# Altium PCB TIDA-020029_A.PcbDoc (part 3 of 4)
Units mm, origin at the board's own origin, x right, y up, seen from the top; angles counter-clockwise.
Board outline 267.5 x 53.5 mm, 2 copper layers (Top Layer, Bottom Layer), stack 1.575 mm thick; 255 components, 134 nets, 990 pads, 1977 vias.
Unrouted connection lines stored in the file: 9.
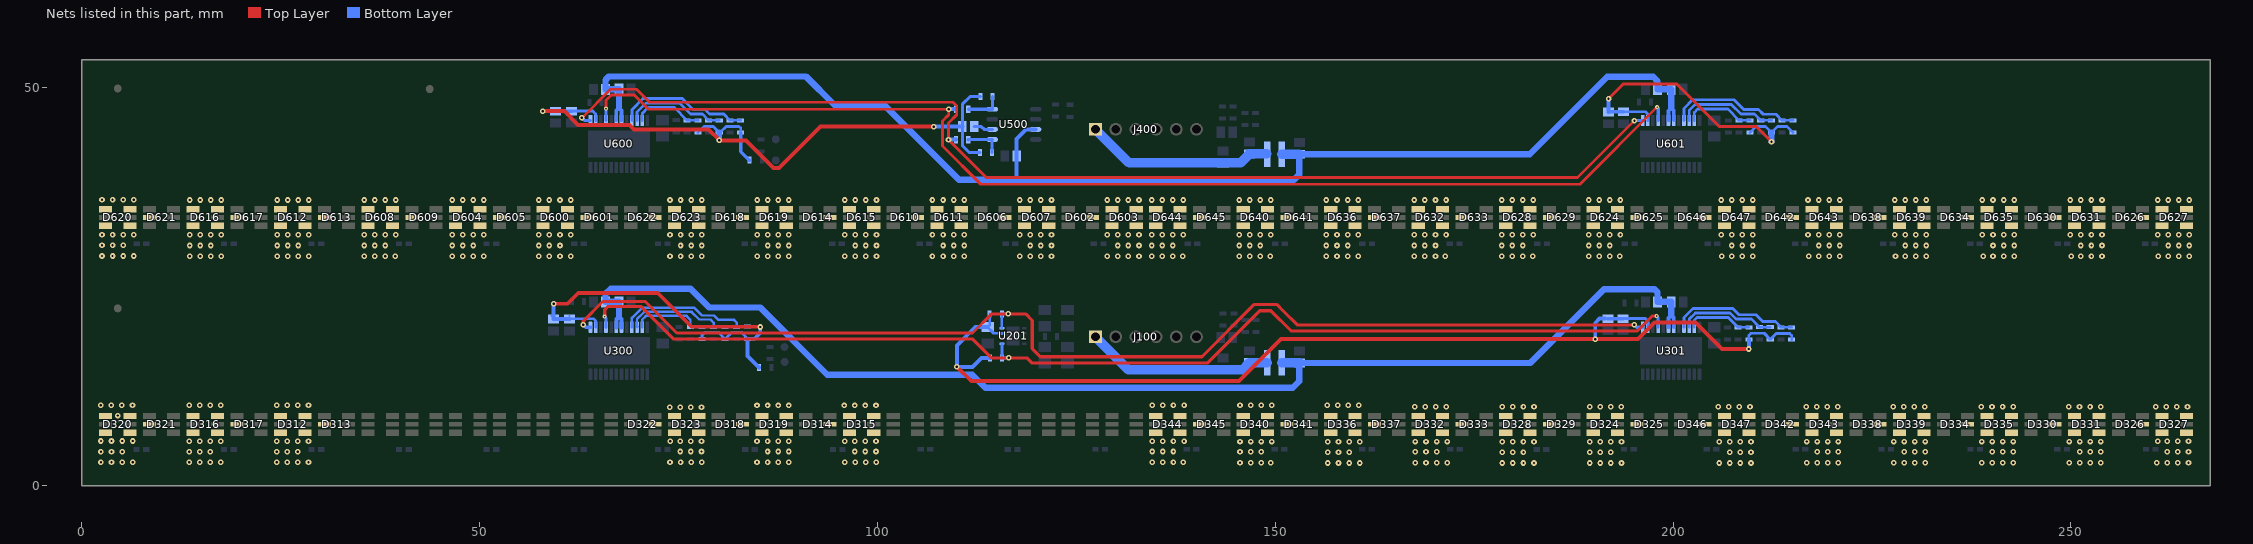
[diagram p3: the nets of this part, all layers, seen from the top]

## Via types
v1: diameter 0.7, hole 0.3, Top Layer to Bottom Layer, tented both sides, 1881 vias
v2: diameter 0.5, hole 0.2, Top Layer to Bottom Layer, tented both sides, 96 vias

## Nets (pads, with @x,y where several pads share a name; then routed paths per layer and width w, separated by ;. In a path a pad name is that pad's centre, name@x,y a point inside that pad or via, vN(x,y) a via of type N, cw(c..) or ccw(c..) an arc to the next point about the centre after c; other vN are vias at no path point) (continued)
NetD312_1: D312.1 D312.3 D312.4 D312.6 D313.2
  other v1: 24.486,2.908 25.815,2.908 27.144,2.908 28.473,2.908 24.486,4.256 25.815,4.256 27.144,4.256 24.486,5.577 25.815,5.577 27.144,5.577 28.473,5.577 24.486,10.098 25.815,10.098 27.144,10.098 28.473,10.098
NetD314_2: D314.2 D315.1 D315.3 D315.4 D315.6
  other v1: 95.86,2.913 97.189,2.913 98.518,2.913 99.847,2.913 97.148,4.281 98.478,4.281 99.807,4.281 95.86,5.577 97.148,5.577 98.478,5.577 99.807,5.577 95.819,10.073 97.148,10.073 98.478,10.073 99.807,10.073
NetD316_1: D316.1 D316.3 D316.4 D316.6 D317.2
  other v1: 13.462,2.908 14.791,2.908 16.121,2.908 17.45,2.908 13.462,4.256 14.791,4.256 16.121,4.256 13.462,5.577 14.791,5.577 16.121,5.577 17.45,5.577 13.462,10.098 14.791,10.098 16.121,10.098 17.45,10.098
NetD318_2: D318.2 D319.1 D319.3 D319.4 D319.6
  other v1: 84.85,2.908 86.179,2.908 87.509,2.908 88.838,2.908 86.179,4.281 87.509,4.281 88.838,4.281 84.85,5.577 86.179,5.577 87.509,5.577 88.838,5.577 84.85,10.073 86.179,10.073 87.509,10.073 88.838,10.073
NetD320_1: D320.1 D320.3 D320.4 D320.6 D321.2
  other v1: 2.388,2.908 3.717,2.908 5.046,2.908 6.375,2.908 2.388,4.256 3.717,4.256 5.046,4.256 2.388,5.602 3.717,5.602 5.046,5.602 6.375,5.602 4.5,8.803 2.362,10.098 3.691,10.098 5.021,10.098 6.35,10.098
NetD322_2: D322.2 D323.1 D323.3 D323.4 D323.6
  other v1: 73.914,2.908 75.243,2.908 76.573,2.908 77.902,2.908 75.218,4.281 76.547,4.281 77.876,4.281 73.939,5.577 75.218,5.577 76.547,5.577 77.876,5.577 73.889,9.869 75.218,9.869 76.547,9.869 77.876,9.869
NetD324_1: D324.1 D324.3 D324.4 D324.6 D325.2
  other v1: 189.535,2.84 190.864,2.84 192.193,2.84 193.523,2.84 189.535,4.213 190.864,4.213 192.193,4.213 189.535,5.509 190.864,5.509 192.193,5.509 193.523,5.509 189.509,9.898 190.839,9.898 192.168,9.898 193.497,9.898
NetD326_2: D326.2 D327.1 D327.3 D327.4 D327.6
  other v1: 260.807,2.892 262.136,2.892 263.466,2.892 264.795,2.892 262.136,4.264 263.466,4.264 264.795,4.264 260.907,5.559 262.136,5.559 263.466,5.559 264.795,5.559 260.68,9.898 262.009,9.898 263.339,9.898 264.668,9.898
NetD328_1: D328.1 D328.3 D328.4 D328.6 D329.2
  other v1: 178.537,2.84 179.866,2.84 181.195,2.84 182.524,2.84 178.537,4.213 179.866,4.213 181.195,4.213 178.537,5.509 179.866,5.509 181.195,5.509 182.524,5.509 178.537,9.898 179.866,9.898 181.195,9.898 182.524,9.898
NetD330_2: D330.2 D331.1 D331.3 D331.4 D331.6
  other v1: 249.784,2.867 251.113,2.867 252.442,2.867 253.771,2.867 251.113,4.239 252.442,4.239 253.771,4.239 249.784,5.534 251.113,5.534 252.442,5.534 253.771,5.534 249.758,9.898 251.087,9.898 252.417,9.898 253.746,9.898
NetD332_1: D332.1 D332.3 D332.4 D332.6 D333.2
  other v1: 167.615,2.865 168.944,2.865 170.273,2.865 171.602,2.865 167.615,4.239 168.944,4.239 170.273,4.239 167.615,5.534 168.944,5.534 170.273,5.534 171.602,5.534 167.513,9.898 168.842,9.898 170.172,9.898 171.501,9.898
NetD334_2: D334.2 D335.1 D335.3 D335.4 D335.6
  other v1: 238.785,2.867 240.115,2.867 241.444,2.867 242.773,2.867 240.115,4.239 241.444,4.239 242.773,4.239 238.785,5.534 240.115,5.534 241.444,5.534 242.773,5.534 238.76,9.898 240.089,9.898 241.419,9.898 242.748,9.898
NetD336_1: D336.1 D336.3 D336.4 D336.6 D337.2
  other v1: 156.616,2.84 157.946,2.84 159.275,2.84 160.604,2.84 156.616,4.213 157.946,4.213 159.275,4.213 156.616,5.509 157.946,5.509 159.275,5.509 160.604,5.509 156.515,10.098 157.844,10.098 159.173,10.098 160.503,10.098
NetD338_2: D338.2 D339.1 D339.3 D339.4 D339.6
  other v1: 227.736,2.867 229.066,2.867 230.395,2.867 231.724,2.867 229.066,4.239 230.395,4.239 231.724,4.239 227.736,5.534 229.066,5.534 230.395,5.534 231.724,5.534 227.66,9.898 228.989,9.898 230.319,9.898 231.648,9.898
NetD340_1: D340.1 D340.3 D340.4 D340.6 D341.2
  other v1: 145.567,2.865 146.897,2.865 148.226,2.865 149.455,2.865 145.567,4.239 146.897,4.239 148.226,4.239 145.567,5.534 146.897,5.534 148.226,5.534 149.555,5.534 145.567,10.098 146.897,10.098 148.226,10.098 149.555,10.098
NetD342_2: D342.2 D343.1 D343.3 D343.4 D343.6
  other v1: 216.786,2.867 218.115,2.867 219.445,2.867 220.774,2.867 218.115,4.239 219.445,4.239 220.774,4.239 216.786,5.534 218.115,5.534 219.445,5.534 220.774,5.534 216.738,9.898 218.067,9.898 219.397,9.898 220.726,9.898
NetD344_1: D344.1 D344.3 D344.4 D344.6 D345.2
  other v1: 134.544,2.908 135.873,2.908 137.202,2.908 138.432,2.908 134.544,4.281 135.873,4.281 137.202,4.281 134.544,5.577 135.873,5.577 137.202,5.577 138.532,5.577 134.544,10.098 135.873,10.098 137.202,10.098 138.532,10.098
NetD346_2: D346.2 D347.1 D347.3 D347.4 D347.6
  other v1: 205.811,2.842 207.141,2.842 208.47,2.842 209.799,2.842 207.141,4.213 208.47,4.213 209.799,4.213 205.811,5.509 207.141,5.509 208.47,5.509 209.799,5.509 205.685,9.898 207.014,9.898 208.344,9.898 209.673,9.898
NetD600_1: D600.1 D600.3 D600.4 D600.6 D601.2
  other v1: 57.429,28.834 58.758,28.834 60.087,28.834 61.417,28.834 57.429,30.182 58.758,30.182 60.087,30.182 57.429,31.528 58.758,31.528 60.087,31.528 61.417,31.528 57.429,35.897 58.758,35.897 60.087,35.897 61.417,35.897
NetD602_2: D602.2 D603.1 D603.3 D603.4 D603.6
  other v1: 128.88,28.834 130.209,28.834 131.538,28.834 132.867,28.834 130.209,30.182 131.538,30.182 132.867,30.182 128.88,31.528 130.209,31.528 131.538,31.528 132.867,31.528 128.88,35.897 130.209,35.897 131.538,35.897 132.867,35.897
NetD604_1: D604.1 D604.3 D604.4 D604.6 D605.2
  other v1: 46.526,28.834 47.855,28.834 49.184,28.834 50.514,28.834 46.526,30.182 47.855,30.182 49.184,30.182 46.526,31.528 47.855,31.528 49.184,31.528 50.514,31.528 46.526,35.897 47.855,35.897 49.184,35.897 50.514,35.897
NetD606_2: D606.2 D607.1 D607.3 D607.4 D607.6
  other v1: 117.881,28.834 119.211,28.834 120.54,28.834 121.869,28.834 119.211,30.182 120.54,30.182 121.869,30.182 117.881,31.528 119.211,31.528 120.54,31.528 121.869,31.528 117.881,35.897 119.211,35.897 120.54,35.897 121.869,35.897
NetD608_1: D608.1 D608.3 D608.4 D608.6 D609.2
  other v1: 35.479,28.834 36.808,28.834 38.137,28.834 39.367,28.834 35.479,30.182 36.808,30.182 38.137,30.182 35.479,31.528 36.808,31.528 38.137,31.528 39.467,31.528 35.479,35.897 36.808,35.897 38.137,35.897 39.467,35.897
NetD610_2: D610.2 D611.1 D611.3 D611.4 D611.6
  other v1: 106.909,28.834 108.238,28.834 109.567,28.834 110.896,28.834 108.238,30.182 109.567,30.182 110.896,30.182 106.909,31.528 108.238,31.528 109.567,31.528 110.896,31.528 106.909,35.897 108.238,35.897 109.567,35.897 110.896,35.897
NetD612_1: D612.1 D612.3 D612.4 D612.6 D613.2
  other v1: 24.529,28.834 25.859,28.834 27.188,28.834 28.517,28.834 24.529,30.182 25.859,30.182 27.188,30.182 24.529,31.528 25.859,31.528 27.188,31.528 28.517,31.528 24.529,35.897 25.859,35.897 27.188,35.897 28.517,35.897
NetD614_2: D614.2 D615.1 D615.3 D615.4 D615.6
  other v1: 95.885,28.834 97.214,28.834 98.544,28.834 99.873,28.834 97.214,30.182 98.544,30.182 99.873,30.182 95.885,31.528 97.214,31.528 98.544,31.528 99.873,31.528 95.885,35.897 97.214,35.897 98.544,35.897 99.873,35.897
NetD616_1: D616.1 D616.3 D616.4 D616.6 D617.2
  other v1: 13.531,28.834 14.86,28.834 16.19,28.834 17.519,28.834 13.531,30.182 14.86,30.182 16.19,30.182 13.531,31.528 14.86,31.528 16.19,31.528 17.519,31.528 13.531,35.897 14.86,35.897 16.19,35.897 17.519,35.897
NetD618_2: D618.2 D619.1 D619.3 D619.4 D619.6
  other v1: 84.861,28.834 86.191,28.834 87.52,28.834 88.849,28.834 86.191,30.182 87.52,30.182 88.849,30.182 84.861,31.528 86.191,31.528 87.52,31.528 88.849,31.528 84.861,35.897 86.191,35.897 87.52,35.897 88.849,35.897
NetD620_1: D620.1 D620.3 D620.4 D620.6 D621.2
  other v1: 2.515,28.859 3.844,28.859 5.173,28.859 6.502,28.859 2.515,30.207 3.844,30.207 5.173,30.207 2.515,31.553 3.844,31.553 5.173,31.553 6.502,31.553 2.515,35.922 3.844,35.922 5.173,35.922 6.502,35.922
NetD622_2: D622.2 D623.1 D623.3 D623.4 D623.6
  other v1: 73.914,28.834 75.243,28.834 76.573,28.834 77.902,28.834 75.243,30.182 76.573,30.182 77.902,30.182 73.914,31.528 75.243,31.528 76.573,31.528 77.902,31.528 73.914,35.897 75.243,35.897 76.573,35.897 77.902,35.897
NetD624_1: D624.1 D624.3 D624.4 D624.6 D625.2
  other v1: 189.401,28.834 190.73,28.834 192.059,28.834 193.289,28.834 189.401,30.182 190.73,30.182 192.059,30.182 189.401,31.528 190.73,31.528 192.059,31.528 193.389,31.528 189.401,35.897 190.73,35.897 192.059,35.897 193.389,35.897
NetD626_2: D626.2 D627.1 D627.3 D627.4 D627.6
  other v1: 261.009,28.834 262.238,28.834 263.567,28.834 264.897,28.834 262.238,30.182 263.567,30.182 264.897,30.182 260.909,31.528 262.238,31.528 263.567,31.528 264.897,31.528 260.909,35.897 262.238,35.897 263.567,35.897 264.897,35.897
NetD628_1: D628.1 D628.3 D628.4 D628.6 D629.2
  other v1: 178.453,28.834 179.783,28.834 181.112,28.834 182.341,28.834 178.453,30.182 179.783,30.182 181.112,30.182 178.453,31.528 179.783,31.528 181.112,31.528 182.441,31.528 178.453,35.897 179.783,35.897 181.112,35.897 182.441,35.897
NetD630_2: D630.2 D631.1 D631.3 D631.4 D631.6
  other v1: 250.036,28.834 251.265,28.834 252.595,28.834 253.924,28.834 251.265,30.182 252.595,30.182 253.924,30.182 249.936,31.528 251.265,31.528 252.595,31.528 253.924,31.528 249.936,35.897 251.265,35.897 252.595,35.897 253.924,35.897
NetD632_1: D632.1 D632.3 D632.4 D632.6 D633.2
  other v1: 167.479,28.834 168.808,28.834 170.137,28.834 171.367,28.834 167.479,30.182 168.808,30.182 170.137,30.182 167.479,31.528 168.808,31.528 170.137,31.528 171.467,31.528 167.479,35.897 168.808,35.897 170.137,35.897 171.467,35.897
NetD634_2: D634.2 D635.1 D635.3 D635.4 D635.6
  other v1: 238.987,28.834 240.216,28.834 241.546,28.834 242.875,28.834 240.216,30.182 241.546,30.182 242.875,30.182 238.887,31.528 240.216,31.528 241.546,31.528 242.875,31.528 238.887,35.897 240.216,35.897 241.546,35.897 242.875,35.897
NetD636_1: D636.1 D636.3 D636.4 D636.6 D637.2
  other v1: 156.429,28.834 157.758,28.834 159.087,28.834 160.417,28.834 156.429,30.182 157.758,30.182 159.087,30.182 156.429,31.528 157.758,31.528 159.087,31.528 160.417,31.528 156.429,35.897 157.758,35.897 159.087,35.897 160.417,35.897
NetD638_2: D638.2 D639.1 D639.3 D639.4 D639.6
  other v1: 227.963,28.834 229.193,28.834 230.522,28.834 231.851,28.834 229.193,30.182 230.522,30.182 231.851,30.182 227.863,31.528 229.193,31.528 230.522,31.528 231.851,31.528 227.863,35.897 229.193,35.897 230.522,35.897 231.851,35.897
NetD640_1: D640.1 D640.3 D640.4 D640.6 D641.2
  other v1: 145.459,28.834 146.788,28.834 148.117,28.834 149.347,28.834 145.459,30.182 146.788,30.182 148.117,30.182 145.459,31.528 146.788,31.528 148.117,31.528 149.447,31.528 145.459,35.897 146.788,35.897 148.117,35.897 149.447,35.897
NetD642_2: D642.2 D643.1 D643.3 D643.4 D643.6
  other v1: 217.067,28.834 218.296,28.834 219.625,28.834 220.955,28.834 218.296,30.182 219.625,30.182 220.955,30.182 216.967,31.528 218.296,31.528 219.625,31.528 220.955,31.528 216.967,35.897 218.296,35.897 219.625,35.897 220.955,35.897
NetD644_1: D644.1 D644.3 D644.4 D644.6 D645.2
  other v1: 134.461,28.834 135.79,28.834 137.119,28.834 138.348,28.834 134.461,30.182 135.79,30.182 137.119,30.182 134.461,31.528 135.79,31.528 137.119,31.528 138.448,31.528 134.461,35.897 135.79,35.897 137.119,35.897 138.448,35.897
NetD646_2: D646.2 D647.1 D647.3 D647.4 D647.6
  other v1: 206.145,28.834 207.374,28.834 208.703,28.834 210.033,28.834 207.374,30.182 208.703,30.182 210.033,30.182 206.045,31.528 207.374,31.528 208.703,31.528 210.033,31.528 206.045,35.897 207.374,35.897 208.703,35.897 210.033,35.897
NetR300_1: R300.1 R303.2 U300.9 | length 17.6
  Bottom Layer w0.254: R303.2@82.3,19.962 R300.1@83.75,19.962
  Bottom Layer w0.3: U300.9@69.125,19.9 69.125,21.075 70.38,22.33 76.995,22.33 77.95,21.375 79.455,21.375 80,20.83 81.97,20.83 82.3,20.5 R303.2@82.3,19.962
NetR301_1: R301.1 R304.2 U300.10 | length 13.7
  Bottom Layer w0.254: U300.10@69.775,19.9 U300.10@69.873,19.998 ; R304.2@79.4,19.962 R301.1@80.85,19.962
  Bottom Layer w0.3: U300.10@69.775,19.9 69.775,20.932 70.672,21.83 76.635,21.83 77.59,20.875 78.991,20.875 79.4,20.466 R304.2@79.4,19.962
NetR302_1: R302.1 R305.2 U300.11 | length 9.8
  Bottom Layer w0.254: R305.2@76.5,19.962 R302.1@77.95,19.962
  Bottom Layer w0.3: U300.11@70.425,19.9 70.425,20.875 70.88,21.33 76,21.33 76.5,20.83 R305.2@76.5,19.962
NetR310_1: R310.1 R313.2 U301.9 | length 16.2
  Bottom Layer w0.35: U301.9@201.375,19.9 201.375,21.139 202.494,22.258 207.503,22.258 208.284,21.477 210.412,21.477 211.281,20.607 212.856,20.607 R313.2@213.567,19.896 R310.1@214.913,19.896
NetR311_1: R311.1 R314.2 U301.10 | length 12.3
  Bottom Layer w0.35: U301.10@202.025,19.9 202.025,20.927 202.035,20.927 202.798,21.69 207.169,21.69 207.933,20.927 209.854,20.927 R314.2@210.875,19.906 R311.1@212.221,19.906
NetR312_1: R312.1 R315.2 U301.11 | length 8.4
  Bottom Layer w0.254: R312.1@209.527,19.897 R312.1@209.529,19.896
  Bottom Layer w0.35: U301.11@202.675,19.9 202.675,20.789 203.026,21.14 206.942,21.14 R315.2@208.185,19.897 R312.1@209.527,19.897
NetR500_2: R500.2 U500.2 | length 2.4
  Bottom Layer w0.4: R500.2@112.154,45.125 113.045,45.125 113.401,44.769 U500.2@114.42,44.769
NetR501_1: R501.1 R503.2 U500.1 | length 4.7
  Bottom Layer w0.254: R503.2@111.608,43.474 R503.2@111.633,43.499 ; U500.1@114.402,43.481 U500.1@114.42,43.499
  Bottom Layer w0.4: R503.2@111.408,43.474 U500.1@114.42,43.499 ; R501.1@114.402,41.873 U500.1@114.402,43.481
NetR502_1: R502.1 R504.2 U500.4 | length 4.6
  Bottom Layer w0.254: U500.4@114.42,47.309 U500.4@114.452,47.342
  Bottom Layer w0.4: R504.2@111.43,47.309 U500.4@114.42,47.309 ; U500.4@114.452,47.342 R502.1@114.452,48.909
NetR600_1: R600.1 R603.2 U600.9 | length 16.7
  Bottom Layer w0.35: U600.9@69.125,45.9 69.125,47.244 70.536,48.655 75.463,48.655 76.822,47.297 78.295,47.297 78.892,46.699 80.67,46.699 R603.2@81.458,45.912 R600.1@82.804,45.912
NetR601_1: R601.1 R604.2 U600.10 | length 12.7
  Bottom Layer w0.35: U600.10@69.775,45.9 69.775,46.955 70.891,48.071 75.108,48.071 76.479,46.699 77.978,46.699 R604.2@78.765,45.912 R601.1@80.112,45.912
NetR602_1: R602.1 R605.2 U600.11 | length 8.8
  Bottom Layer w0.35: U600.11@70.425,45.9 70.425,46.766 71.171,47.512 74.473,47.512 R605.2@76.073,45.912 R602.1@77.419,45.912
NetR610_1: R610.1 R613.2 U601.9 | length 16.7
  Bottom Layer w0.35: U601.9@201.375,45.9 201.375,47.41 202.467,48.503 207.649,48.503 208.894,47.258 210.748,47.258 211.332,46.674 212.958,46.674 R613.2@213.72,45.912 R610.1@215.066,45.912
NetR611_1: R611.1 R614.2 U601.10 | length 12.8
  Bottom Layer w0.35: U601.10@202.025,45.9 202.025,47.171 202.772,47.919 207.319,47.919 208.538,46.699 210.24,46.699 R614.2@211.027,45.912 R611.1@212.373,45.912
NetR612_1: R612.1 R615.2 U601.11 | length 8.8
  Bottom Layer w0.35: U601.11@202.675,45.9 202.675,46.907 203.094,47.326 206.895,47.326 R615.2@208.309,45.912 R612.1@209.681,45.912
RxD: R206.1 R503.1 U201.4 U300.1 U301.1 U600.1 U601.1 | length 297.7
  Top Layer w0.35: v1(62.84,46.217) 66.446,49.824 69.707,49.824 71.34,48.19 109.478,48.19 109.957,47.711 109.957,46.608 108.922,45.574 v1(108.922,43.474) 113.675,38.721 187.99,38.721 v1(195.148,45.879)
  Top Layer w0.4: v1(63.016,20.2) 63.016,20.676 65.477,23.136 70.815,23.136 74.778,19.174 111.938,19.174 114.351,21.587 v1(116.442,21.587) 118.623,21.587 119.456,20.753 119.456,17.218 120.472,16.202 140.792,16.202 147.371,22.781 150.165,22.781 151.028,21.917 152.745,20.201 v1(195.127,20.201)
  Bottom Layer w0.254: U201.4@115.621,19.816 U201.4@115.643,19.794 ; R206.1@115.621,21.572 R206.1@115.635,21.587
  Bottom Layer w0.35: U201.4@115.621,19.816 R206.1@115.621,21.572 ; R206.1@115.635,21.587 v1(116.442,21.587)
  Bottom Layer w0.4: v1(62.84,46.217) 63.156,45.9 U600.1@63.925,45.9 ; v1@195.121,45.9 U601.1@196.175,45.9
  Bottom Layer w0.45: v1(63.016,20.2) 63.316,19.9 U300.1@63.925,19.9 ; v1(195.127,20.201) 195.427,19.9 U301.1@196.175,19.9
  Bottom Layer w0.5: v1(108.922,43.474) R503.1@109.884,43.474
TxD: R205.1 R504.1 U201.1 U300.4 U301.4 U600.4 U601.4 | length 296.4
  Top Layer w0.35: v2(65.875,47.37) 65.875,48.432 66.542,49.099 69.426,49.099 71.215,47.309 v1(108.951,47.309) 108.951,46.616 108.153,45.818 108.153,42.704 112.979,37.878 188.295,37.878 v2(197.993,47.576)
  Top Layer w0.4: v2(65.709,21.241) 65.709,22.097 66.138,22.527 70.242,22.527 74.331,18.437 111.912,18.437 114.3,16.05 v1(116.484,16.05) 118.768,16.05 119.429,15.389 141.453,15.389 148.031,21.968 149.454,21.968 151.994,19.428 195.512,19.428 197.394,21.311 v2(197.95,21.311)
  Bottom Layer w0.254: U201.1@115.643,17.844 U201.1@115.646,17.841 ; R205.1@115.646,16.048 R205.1@115.647,16.05
  Bottom Layer w0.35: R205.1@115.646,16.048 U201.1@115.646,17.841 ; R205.1@115.647,16.05 v1(116.484,16.05) ; v2(197.95,21.311) 198.125,21.135 U301.4@198.125,19.9
  Bottom Layer w0.4: v2(65.709,21.241) 65.875,21.075 U300.4@65.875,19.9 ; U600.4@65.875,45.9 v2(65.875,47.37)
  Bottom Layer w0.45: v2(197.993,47.576) 198.125,47.444 U601.4@198.125,45.9
  Bottom Layer w0.5: v1(108.951,47.309) R504.1@109.884,47.309
VCC1: C305.1 C306.1 C605.1 C606.1 R300.2 R301.2 R302.2 R308.2 R500.1 R501.2 R502.2 R600.2 R601.2 R602.2 R608.2 U300.2 U600.2 | length 138.5
  Top Layer w0.45: v1(59.281,22.879) 61.059,22.879 62.382,24.203 72.361,24.203 76.614,19.95 v1@85.268,19.95
  Top Layer w0.5: v1(57.937,47.061) 60.645,47.061 62.378,45.328 68.838,45.328 69.379,44.787 78.74,44.787 v1(80.112,43.415) 80.137,43.39 83.472,43.39 86.952,39.91 87.593,39.91 92.808,45.125 v1(107.079,45.125)
  Bottom Layer w0.254: C306.1@59.027,21.33 C306.1@59.031,21.334 ; C305.1@61.265,21.318 C305.1@61.281,21.334 ; R500.1@110.665,45.114 R500.1@110.654,45.125 R500.1@110.665,45.135
  Bottom Layer w0.35: C305.1@61.263,20.98 64.32,20.98 64.575,20.726 U300.2@64.575,19.9 ; C606.1@61.519,47.073 64.211,47.073 64.575,46.709 U600.2@64.575,45.9 ; R602.2@77.419,44.388 78.174,45.142 79.357,45.142 R601.2@80.112,44.388 80.221,44.388 80.983,45.15 82.593,45.15 82.804,44.939 R600.2@82.804,44.388 ; R302.2@77.95,18.438 77.95,18.9 78.25,19.2 80.088,19.2 R301.2@80.85,18.438 81.612,19.2 82.988,19.2 R300.2@83.74,18.448
  Bottom Layer w0.4: R600.2@82.804,44.388 82.804,41.986 83.89,40.901 R608.2@83.931,40.901 ; R500.1@110.665,45.114 110.665,42.751 111.542,41.873 R501.2@112.878,41.873 ; R500.1@110.665,45.135 110.665,47.915 111.658,48.909 R502.2@112.928,48.909
  Bottom Layer w0.45: C605.1@59.546,47.061 C606.1@61.546,47.061 ; R300.2@83.648,18.448 83.74,18.448 84.536,18.448 85.268,19.179 v1(85.268,19.936)
  Bottom Layer w0.5: v1(57.937,47.061) C605.1@59.546,47.061 ; C306.1@59.279,20.943 C306.1@59.281,20.943 ; C306.1@59.281,20.938 C306.1@59.281,20.943 ; v1(59.281,22.879) C306.1@59.281,20.943 ; C305.1@61.263,20.943 C306.1@59.281,20.943 ; R300.2@83.648,18.448 83.648,16.303 84.264,15.688 85.108,14.842 R308.2@85.132,14.842 ; v1(107.079,45.125) R500.1@110.654,45.125
  Bottom Layer w0.7: v1(80.112,43.415) R601.2@80.112,44.388
VCC2: C204.1 C322.1 C323.1 C622.1 C623.1 R205.2 R206.2 R310.2 R311.2 R312.2 R610.2 R611.2 R612.2 U201.3 U301.2 U601.2 | length 178
  Top Layer w0.4: v1(191.893,48.618) 193.751,50.476 200.459,50.476 205.793,45.142 210.464,45.142 v1(212.373,43.233)
  Top Layer w0.5: v1(109.982,14.932) 111.785,13.129 145.415,13.129 150.698,18.412 v1(190.221,18.412) 195.606,18.412 197.689,20.495 202.819,20.495 206.145,17.169 v1(209.529,17.169)
  Bottom Layer w0.35: R206.2@114.097,21.572 114.097,20.165 C204.1@113.843,19.911 114.61,19.144 U201.3@115.643,19.144 ; C323.1@193.764,20.989 196.536,20.989 196.825,20.701 U301.2@196.825,19.9 ; C623.1@193.777,46.997 196.52,46.997 196.825,46.691 U601.2@196.825,45.9 ; R312.2@209.529,18.372 209.529,18.865 209.808,19.144 211.459,19.144 R311.2@212.221,18.382 212.973,19.134 214.659,19.134 214.913,18.88 R310.2@214.913,18.372 ; R612.2@209.681,44.388 210.443,45.15 211.611,45.15 R611.2@212.373,44.388 213.135,45.15 214.304,45.15 R610.2@215.066,44.388
  Bottom Layer w0.45: C322.1@191.828,20.968 C323.1@193.73,20.968 ; C622.1@191.893,46.967 C623.1@193.794,46.967
  Bottom Layer w0.5: C204.1@113.843,19.911 112.287,19.911 109.982,17.607 v1(109.982,14.932) 111.938,14.932 113.054,16.048 R205.2@114.097,16.048 ; v1(190.221,18.412) 190.221,20.422 190.779,20.98 C322.1@191.434,20.98 ; C622.1@191.893,46.967 v1(191.893,48.618) ; v1(209.529,17.169) R312.2@209.529,18.372
  Bottom Layer w0.7: v1(212.373,43.233) R611.2@212.373,44.388
Vsup: C102.1 C300.1 C301.1 C317.1 C318.1 C402.1 C500.1 C600.1 C601.1 C617.1 C618.1 L100.2 L400.2 U300.6 U300.7 U301.6 U301.7 U500.7 U600.6 U600.7 U601.6 U601.7 | length 334.3
  Bottom Layer w0.254: C601.1@65.806,49.798 C601.1@65.831,49.824 ; C102.1@153.022,15.425 C102.1@153.035,15.412
  Bottom Layer w0.35: 117.5,38.451 117.514,38.437
  Bottom Layer w0.45: U600.6@67.175,45.9 67.175,47.181 67.506,47.512 67.825,47.193 U600.7@67.825,45.9 ; U301.6@199.425,19.9 199.425,21.071 ; U601.6@199.425,45.9 199.425,47.111 199.77,47.456 200.075,47.151 U601.7@200.075,45.9 ; U301.7@200.075,19.9 200.075,21.11
  Bottom Layer w0.5: U300.6@67.2,19.9 67.2,20.938 67.506,21.244 67.8,20.95 U300.7@67.8,19.9 ; 117.5,38.451 C500.1@117.5,41.448 117.5,43.575 118.694,44.769 U500.7@119.87,44.769 ; 199.425,21.071 199.77,21.416 200.075,21.11
  Bottom Layer w0.8: C601.1@65.806,49.798 65.806,50.986 66.238,51.419 91.015,51.419 94.555,47.879 100.809,47.879 110.251,38.437 117.514,38.437 152.349,38.437 153.035,39.123 C402.1@153.035,41.635 181.988,41.635 191.745,51.391 197.492,51.391 198.044,50.839 C617.1@198.044,49.824 C618.1@199.77,49.824 199.77,47.456 ; C601.1@65.831,49.824 C600.1@67.506,49.824 67.506,47.512 ; 67.506,21.244 C301.1@67.506,23.096 C300.1@65.806,23.096 65.806,24.096 66.472,24.762 76.49,24.762 78.867,22.385 85.261,22.385 93.324,14.322 ; 93.32,14.322 93.324,14.322 ; 199.77,21.416 C318.1@199.77,23.096 C317.1@198.044,23.096 198.044,24.305 197.663,24.686 191.313,24.686 182.039,15.412 C102.1@153.035,15.412 153.035,13.129 152.197,12.29 113.569,12.29 111.918,13.941 93.705,13.941 93.324,14.322
  Bottom Layer w1.2: L100.2@150.8,15.425 C102.1@153.022,15.425 ; L400.2@150.8,41.635 C402.1@153.035,41.635
Vsupply: C100.1 C101.1 C400.1 C401.1 J100.1 J400.1 L100.1 L400.1 | length 47.6
  Bottom Layer w0.254: L400.1@148.949,41.685 L400.1@149,41.635 ; L100.1@148.963,15.463 L100.1@149,15.425
  Bottom Layer w1.2: J100.1@127.4,18.7 131.552,14.548 C100.1@143.408,14.548 145.847,14.548 C101.1@146.761,15.463 L100.1@148.963,15.463 ; J400.1@127.4,44.782 131.623,40.558 C400.1@143.408,40.558 145.634,40.558 C401.1@146.761,41.685 L400.1@148.949,41.685
pads on no net: D300.5 D301.5 D302.5 D303.5 D304.5 D305.5 D306.5 D307.5 D308.5 D309.5 D310.5 D311.5 D312.5 D313.5 D314.5 D315.5 D316.5 D317.5 D318.5 D319.5 D320.5 D321.5 D322.5 D323.5 D324.5 D325.5 D326.5 D327.5 D328.5 D329.5 D330.5 D331.5 D332.5 D333.5 D334.5 D335.5 D336.5 D337.5 D338.5 D339.5 D340.5 D341.5 D342.5 D343.5 D344.5 D345.5 D346.5 D347.5 D600.5 D601.5 D602.5 D603.5 D604.5 D605.5 D606.5 D607.5 D608.5 D609.5 D610.5 D611.5 D612.5 D613.5 D614.5 D615.5 D616.5 D617.5 D618.5 D619.5 D620.5 D621.5 D622.5 D623.5 D624.5 D625.5 D626.5 D627.5 D628.5 D629.5 D630.5 D631.5 D632.5 D633.5 D634.5 D635.5 D636.5 D637.5 D638.5 D639.5 D640.5 D641.5 D642.5 D643.5 D644.5 D645.5 D646.5 D647.5 FID1.1 FID2.1 FID3.1 J400.3 U201.5 U201.9@117.043,18.184 U201.9@117.043,19.454 U500.3 U500.8

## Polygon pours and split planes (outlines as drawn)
GND on Top Layer "TOP_LAYER_GND_P410" (solid, remove dead copper, pour order 410): 0.26,51.086 1.784,52.61 265.69,52.61 267.214,51.086 267.214,27.21 266.96,26.956 0.514,26.956 0.26,27.21
NetD626_2 on Top Layer "TOP_LAYER_NETD626_2_P310" (solid, remove dead copper, pour order 310): 265.43,36.887 265.43,27.745 259.973,27.745 259.973,33.079 257.861,33.079 257.861,34.349 259.973,34.349 259.973,36.887
4OUT0 on Top Layer "TOP_LAYER_4OUT0_P308" (solid, remove dead copper, pour order 308): 254.762,36.887 254.762,27.743 259.842,27.743 259.842,33.077 257.656,33.077 257.656,34.347 259.842,34.347 259.842,36.887
NetD630_2 on Top Layer "TOP_LAYER_NETD630_2_P306" (solid, remove dead copper, pour order 306): 254.432,36.89 254.432,27.748 248.975,27.748 248.975,33.082 246.863,33.082 246.863,34.352 248.975,34.352 248.975,36.89
4OUT1 on Top Layer "TOP_LAYER_4OUT1_P304" (solid, remove dead copper, pour order 304): 243.764,36.89 243.764,27.746 248.844,27.746 248.844,33.08 246.657,33.08 246.657,34.35 248.844,34.35 248.844,36.89
NetD634_2 on Top Layer "TOP_LAYER_NETD634_2_P302" (solid, remove dead copper, pour order 302): 243.434,36.887 243.434,27.745 237.976,27.745 237.976,33.079 235.864,33.079 235.864,34.349 237.976,34.349 237.976,36.887
4OUT2 on Top Layer "TOP_LAYER_4OUT2_P300" (solid, remove dead copper, pour order 300): 232.766,36.887 232.766,27.743 237.846,27.743 237.846,33.077 235.659,33.077 235.659,34.347 237.846,34.347 237.846,36.887
NetD638_2 on Top Layer "TOP_LAYER_NETD638_2_P298" (solid, remove dead copper, pour order 298): 232.433,36.89 232.433,27.748 226.976,27.748 226.976,33.082 224.864,33.082 224.864,34.352 226.976,34.352 226.976,36.89
4OUT3 on Top Layer "TOP_LAYER_4OUT3_P296" (solid, remove dead copper, pour order 296): 221.765,36.89 221.765,27.746 226.845,27.746 226.845,33.08 224.659,33.08 224.659,34.35 226.845,34.35 226.845,36.89
NetD642_2 on Top Layer "TOP_LAYER_NETD642_2_P294" (solid, remove dead copper, pour order 294): 221.437,36.887 221.437,27.745 215.98,27.745 215.98,33.079 213.868,33.079 213.868,34.349 215.98,34.349 215.98,36.887
4OUT4 on Top Layer "TOP_LAYER_4OUT4_P292" (solid, remove dead copper, pour order 292): 210.82,36.887 210.82,27.743 215.849,27.743 215.849,33.077 213.663,33.077 213.663,34.347 215.849,34.347 215.849,36.887
NetD646_2 on Top Layer "TOP_LAYER_NETD646_2_P290" (solid, remove dead copper, pour order 290): 210.558,36.887 210.558,27.745 204.982,27.745 204.982,33.079 202.87,33.079 202.87,34.349 204.982,34.349 204.982,36.887
4OUT5 on Top Layer "TOP_LAYER_4OUT5_P288" (solid, remove dead copper, pour order 288): 199.771,36.887 199.771,27.743 204.851,27.743 204.851,33.077 202.665,33.077 202.665,34.347 204.851,34.347 204.851,36.887
4OUT6 on Top Layer "TOP_LAYER_4OUT6_P286" (solid, remove dead copper, pour order 286): 194.64,36.854 194.64,34.314 196.545,34.314 196.545,33.044 194.64,33.044 194.64,27.71 199.521,27.71 199.521,36.854
NetD624_1 on Top Layer "TOP_LAYER_NETD624_1_P284" (solid, remove dead copper, pour order 284): 194.462,36.854 194.462,34.06 196.342,34.06 196.342,33.345 194.462,33.345 194.462,27.712 188.599,27.712 188.599,36.854
4OUT7 on Top Layer "TOP_LAYER_4OUT7_P282" (solid, remove dead copper, pour order 282): 183.663,36.854 183.663,34.314 185.568,34.314 185.568,33.044 183.663,33.044 183.663,27.71 188.544,27.71 188.544,36.854
NetD628_1 on Top Layer "TOP_LAYER_NETD628_1_P280" (solid, remove dead copper, pour order 280): 183.485,36.854 183.485,34.06 185.364,34.06 185.364,33.345 183.485,33.345 183.485,27.712 177.622,27.712 177.622,36.854
4OUT8 on Top Layer "TOP_LAYER_4OUT8_P278" (solid, remove dead copper, pour order 278): 172.644,36.854 172.644,34.314 174.549,34.314 174.549,33.044 172.644,33.044 172.644,27.71 177.525,27.71 177.525,36.854
NetD632_1 on Top Layer "TOP_LAYER_NETD632_1_P276" (solid, remove dead copper, pour order 276): 172.466,36.854 172.466,34.06 174.346,34.06 174.346,33.345 172.466,33.345 172.466,27.712 166.603,27.712 166.603,36.854
4OUT9 on Top Layer "TOP_LAYER_4OUT9_P274" (solid, remove dead copper, pour order 274): 161.646,36.854 161.646,34.314 163.551,34.314 163.551,33.044 161.646,33.044 161.646,27.71 166.527,27.71 166.527,36.854
NetD636_1 on Top Layer "TOP_LAYER_NETD636_1_P272" (solid, remove dead copper, pour order 272): 161.468,36.854 161.468,34.06 163.347,34.06 163.347,33.345 161.468,33.345 161.468,27.712 155.605,27.712 155.605,36.854
4OUT10 on Top Layer "TOP_LAYER_4OUT10_P270" (solid, remove dead copper, pour order 270): 150.647,36.862 150.647,34.322 152.552,34.322 152.552,33.052 150.647,33.052 150.647,27.718 155.528,27.718 155.528,36.862
NetD640_1 on Top Layer "TOP_LAYER_NETD640_1_P268" (solid, remove dead copper, pour order 268): 150.47,36.862 150.47,34.068 152.349,34.068 152.349,33.353 150.47,33.353 150.47,27.72 144.606,27.72 144.606,36.862
NetD644_1 on Top Layer "TOP_LAYER_NETD644_1_P266" (solid, remove dead copper, pour order 266): 139.467,36.864 139.467,34.07 141.347,34.07 141.347,33.355 139.467,33.355 139.467,27.721 133.604,27.721 133.604,36.864
4OUT11 on Top Layer "TOP_LAYER_4OUT11_P264" (solid, remove dead copper, pour order 264): 139.645,36.864 139.645,34.324 141.55,34.324 141.55,33.054 139.645,33.054 139.645,27.72 144.526,27.72 144.526,36.864
3OUT0 on Top Layer "TOP_LAYER_3OUT0_P258" (solid, remove dead copper, pour order 258): 122.758,36.887 122.758,27.743 127.838,27.743 127.838,33.077 125.652,33.077 125.652,34.347 127.838,34.347 127.838,36.887
NetD602_2 on Top Layer "TOP_LAYER_NETD602_2_P256" (solid, remove dead copper, pour order 256): 133.426,36.887 133.426,27.745 127.787,27.745 127.787,33.079 125.857,33.079 125.857,34.349 127.864,34.349 127.864,36.887
3OUT1 on Top Layer "TOP_LAYER_3OUT1_P254" (solid, remove dead copper, pour order 254): 111.759,36.862 111.759,27.718 116.839,27.718 116.839,33.052 114.652,33.052 114.652,34.322 116.839,34.322 116.839,36.862
NetD606_2 on Top Layer "TOP_LAYER_NETD606_2_P252" (solid, remove dead copper, pour order 252): 122.427,36.862 122.427,27.72 116.788,27.72 116.788,33.054 114.858,33.054 114.858,34.324 116.864,34.324 116.864,36.862
3OUT2 on Top Layer "TOP_LAYER_3OUT2_P250" (solid, remove dead copper, pour order 250): 100.736,36.887 100.736,27.743 105.816,27.743 105.816,33.077 103.63,33.077 103.63,34.347 105.816,34.347 105.816,36.887
NetD610_2 on Top Layer "TOP_LAYER_NETD610_2_P248" (solid, remove dead copper, pour order 248): 111.404,36.887 111.404,27.745 105.766,27.745 105.766,33.079 103.835,33.079 103.835,34.349 105.842,34.349 105.842,36.887
3OUT3 on Top Layer "TOP_LAYER_3OUT3_P246" (solid, remove dead copper, pour order 246): 89.764,36.887 89.764,27.743 94.844,27.743 94.844,33.077 92.657,33.077 92.657,34.347 94.844,34.347 94.844,36.887
NetD614_2 on Top Layer "TOP_LAYER_NETD614_2_P244" (solid, remove dead copper, pour order 244): 100.432,36.887 100.432,27.745 94.793,27.745 94.793,33.079 92.862,33.079 92.862,34.349 94.869,34.349 94.869,36.887
3OUT4 on Top Layer "TOP_LAYER_3OUT4_P242" (solid, remove dead copper, pour order 242): 78.765,36.887 78.765,27.743 83.845,27.743 83.845,33.077 81.659,33.077 81.659,34.347 83.845,34.347 83.845,36.887
NetD618_2 on Top Layer "TOP_LAYER_NETD618_2_P240" (solid, remove dead copper, pour order 240): 89.433,36.887 89.433,27.745 83.795,27.745 83.795,33.079 81.864,33.079 81.864,34.349 83.871,34.349 83.871,36.887
3OUT5 on Top Layer "TOP_LAYER_3OUT5_P238" (solid, remove dead copper, pour order 238): 67.767,36.887 67.767,27.743 72.847,27.743 72.847,33.077 70.661,33.077 70.661,34.347 72.847,34.347 72.847,36.887
NetD622_2 on Top Layer "TOP_LAYER_NETD622_2_P236" (solid, remove dead copper, pour order 236): 78.435,36.887 78.435,27.745 72.796,27.745 72.796,33.079 70.866,33.079 70.866,34.349 72.873,34.349 72.873,36.887
NetD600_1 on Top Layer "TOP_LAYER_NETD600_1_P230" (solid, remove dead copper, pour order 230): 62.472,36.853 62.472,34.059 64.352,34.059 64.352,33.344 62.472,33.344 62.472,27.711 56.681,27.711 56.681,36.853
3OUT6 on Top Layer "TOP_LAYER_3OUT6_P228" (solid, remove dead copper, pour order 228): 62.65,36.853 62.65,34.313 64.555,34.313 64.555,33.043 62.65,33.043 62.65,27.709 67.654,27.709 67.654,36.853
3OUT7 on Top Layer "TOP_LAYER_3OUT7_P226" (solid, remove dead copper, pour order 226): 51.664,36.853 51.664,34.313 53.569,34.313 53.569,33.043 51.664,33.043 51.664,27.709 56.667,27.709 56.667,36.853
NetD604_1 on Top Layer "TOP_LAYER_NETD604_1_P224" (solid, remove dead copper, pour order 224): 51.486,36.853 51.486,34.059 53.365,34.059 53.365,33.344 51.486,33.344 51.486,27.711 45.695,27.711 45.695,36.853
3OUT8 on Top Layer "TOP_LAYER_3OUT8_P222" (solid, remove dead copper, pour order 222): 40.65,36.862 40.65,34.322 42.555,34.322 42.555,33.052 40.65,33.052 40.65,27.718 45.654,27.718 45.654,36.862
NetD608_1 on Top Layer "TOP_LAYER_NETD608_1_P220" (solid, remove dead copper, pour order 220): 40.472,36.862 40.472,34.068 42.352,34.068 42.352,33.353 40.472,33.353 40.472,27.72 34.681,27.72 34.681,36.862
NetD612_1 on Top Layer "TOP_LAYER_NETD612_1_P218" (solid, remove dead copper, pour order 218): 29.489,36.858 29.489,34.064 31.369,34.064 31.369,33.35 29.489,33.35 29.489,27.716 23.698,27.716 23.698,36.858
3OUT9 on Top Layer "TOP_LAYER_3OUT9_P216" (solid, remove dead copper, pour order 216): 29.667,36.858 29.667,34.318 31.572,34.318 31.572,33.049 29.667,33.049 29.667,27.714 34.671,27.714 34.671,36.858
NetD616_1 on Top Layer "TOP_LAYER_NETD616_1_P214" (solid, remove dead copper, pour order 214): 18.466,36.862 18.466,34.068 20.345,34.068 20.345,33.353 18.466,33.353 18.466,27.72 12.7,27.72 12.7,36.862
3OUT10 on Top Layer "TOP_LAYER_3OUT10_P212" (solid, remove dead copper, pour order 212): 18.644,36.862 18.644,34.322 20.549,34.322 20.549,33.052 18.644,33.052 18.644,27.718 23.622,27.718 23.622,36.862
3OUT11 on Top Layer "TOP_LAYER_3OUT11_P210" (solid, remove dead copper, pour order 210): 7.636,36.862 7.636,34.322 9.541,34.322 9.541,33.052 7.636,33.052 7.636,27.718 12.7,27.718 12.7,36.862
NetD620_1 on Top Layer "TOP_LAYER_NETD620_1_P208" (solid, remove dead copper, pour order 208): 7.459,36.862 7.459,34.068 9.338,34.068 9.338,33.353 7.459,33.353 7.459,27.72 1.524,27.72 1.524,36.862
GND on Top Layer "TOP_LAYER_GND_P206" (solid, remove dead copper, pour order 206): 1.632,25.862 265.83,25.862 267.208,24.484 267.208,0.608 266.954,0.354 0.508,0.354 0.254,0.608 0.254,24.484
2OUT7 on Top Layer "TOP_LAYER_2OUT7_P072" (solid, remove dead copper, pour order 72): 183.636,10.86 183.636,8.32 185.541,8.32 185.541,7.05 183.636,7.05 183.636,1.716 188.564,1.716 188.564,10.86
2OUT5 on Top Layer "TOP_LAYER_2OUT5_P100" (solid, remove dead copper, pour order 100): 199.818,10.86 199.818,1.716 204.898,1.716 204.898,7.05 202.712,7.05 202.712,8.32 204.898,8.32 204.898,10.86
NetD346_2 on Top Layer "TOP_LAYER_NETD346_2_P098" (solid, remove dead copper, pour order 98): 210.486,10.86 210.486,1.718 205.029,1.718 205.029,7.052 202.917,7.052 202.917,8.322 205.029,8.322 205.029,10.86
NetD342_2 on Top Layer "TOP_LAYER_NETD342_2_P096" (solid, remove dead copper, pour order 96): 221.564,10.835 221.564,1.692 216.074,1.692 216.074,7.026 214.004,7.026 214.004,8.296 216.074,8.296 216.074,10.835
2OUT4 on Top Layer "TOP_LAYER_2OUT4_P094" (solid, remove dead copper, pour order 94): 210.74,10.835 210.74,1.691 215.871,1.691 215.871,7.025 214.004,7.025 214.004,8.295 215.871,8.295 215.871,10.835
2OUT3 on Top Layer "TOP_LAYER_2OUT3_P092" (solid, remove dead copper, pour order 92): 221.818,10.86 221.818,1.716 226.898,1.716 226.898,7.05 224.939,7.05 224.939,8.32 226.898,8.32 226.898,10.86
2OUT2 on Top Layer "TOP_LAYER_2OUT2_P090" (solid, remove dead copper, pour order 90): 232.818,10.86 232.818,1.716 237.898,1.716 237.898,7.05 235.962,7.05 235.962,8.32 237.898,8.32 237.898,10.86
2OUT1 on Top Layer "TOP_LAYER_2OUT1_P088" (solid, remove dead copper, pour order 88): 243.818,10.86 243.818,1.716 248.898,1.716 248.898,7.05 246.859,7.05 246.859,8.32 248.898,8.32 248.898,10.86
2OUT0 on Top Layer "TOP_LAYER_2OUT0_P086" (solid, remove dead copper, pour order 86): 254.818,10.86 254.818,1.716 259.898,1.716 259.898,7.05 257.933,7.05 257.933,8.32 259.898,8.32 259.898,10.86
NetD338_2 on Top Layer "TOP_LAYER_NETD338_2_P084" (solid, remove dead copper, pour order 84): 232.486,10.86 232.486,1.718 226.847,1.718 226.847,7.052 224.964,7.052 224.964,8.322 226.923,8.322 226.923,10.86
NetD334_2 on Top Layer "TOP_LAYER_NETD334_2_P082" (solid, remove dead copper, pour order 82): 243.561,10.86 243.561,1.718 238.049,1.718 238.049,7.052 236.038,7.052 236.038,8.322 238.049,8.322 238.049,10.86
NetD330_2 on Top Layer "TOP_LAYER_NETD330_2_P080" (solid, remove dead copper, pour order 80): 254.584,10.86 254.584,1.718 249.047,1.718 249.047,7.052 247.037,7.052 247.037,8.322 249.047,8.322 249.047,10.86
NetD326_2 on Top Layer "TOP_LAYER_NETD326_2_P078" (solid, remove dead copper, pour order 78): 265.486,10.86 265.486,1.718 260.045,1.718 260.045,7.052 258.001,7.052 258.001,8.322 260.045,8.322 260.045,10.86
2OUT6 on Top Layer "TOP_LAYER_2OUT6_P076" (solid, remove dead copper, pour order 76): 194.636,10.86 194.636,8.32 196.541,8.32 196.541,7.05 194.636,7.05 194.636,1.716 199.564,1.716 199.564,10.86
NetD324_1 on Top Layer "TOP_LAYER_NETD324_1_P074" (solid, remove dead copper, pour order 74): 194.459,10.86 194.459,8.066 196.338,8.066 196.338,7.351 194.459,7.351 194.459,1.718 188.773,1.718 188.773,10.86
2OUT8 on Top Layer "TOP_LAYER_2OUT8_P070" (solid, remove dead copper, pour order 70): 172.636,10.86 172.636,8.32 174.541,8.32 174.541,7.05 172.636,7.05 172.636,1.716 177.564,1.716 177.564,10.86
2OUT9 on Top Layer "TOP_LAYER_2OUT9_P068" (solid, remove dead copper, pour order 68): 161.636,10.86 161.636,8.32 163.541,8.32 163.541,7.05 161.636,7.05 161.636,1.716 166.564,1.716 166.564,10.86
2OUT10 on Top Layer "TOP_LAYER_2OUT10_P066" (solid, remove dead copper, pour order 66): 150.636,10.86 150.636,8.32 152.541,8.32 152.541,7.05 150.636,7.05 150.636,1.716 155.564,1.716 155.564,10.86
2OUT11 on Top Layer "TOP_LAYER_2OUT11_P064" (solid, remove dead copper, pour order 64): 139.636,10.86 139.636,8.32 141.541,8.32 141.541,7.05 139.636,7.05 139.636,1.716 144.564,1.716 144.564,10.86
NetD328_1 on Top Layer "TOP_LAYER_NETD328_1_P062" (solid, remove dead copper, pour order 62): 183.459,10.86 183.459,8.066 185.338,8.066 185.338,7.351 183.459,7.351 183.459,1.718 177.72,1.718 177.72,10.86
NetD332_1 on Top Layer "TOP_LAYER_NETD332_1_P060" (solid, remove dead copper, pour order 60): 172.459,10.86 172.459,8.066 174.338,8.066 174.338,7.351 172.459,7.351 172.459,1.718 166.798,1.718 166.798,10.86
NetD336_1 on Top Layer "TOP_LAYER_NETD336_1_P058" (solid, remove dead copper, pour order 58): 161.459,10.86 161.459,8.066 163.338,8.066 163.338,7.351 161.459,7.351 161.459,1.718 155.876,1.718 155.876,10.86
NetD340_1 on Top Layer "TOP_LAYER_NETD340_1_P056" (solid, remove dead copper, pour order 56): 150.459,10.86 150.459,8.066 152.338,8.066 152.338,7.351 150.459,7.351 150.459,1.718 144.7,1.718 144.7,10.86
NetD344_1 on Top Layer "TOP_LAYER_NETD344_1_P054" (solid, remove dead copper, pour order 54): 139.459,10.86 139.459,8.066 141.338,8.066 141.338,7.351 139.459,7.351 139.459,1.718 133.524,1.718 133.524,10.86
NetD320_1 on Top Layer "TOP_LAYER_NETD320_1_P052" (solid, remove dead copper, pour order 52): 7.459,10.86 7.459,8.066 9.338,8.066 9.338,7.351 7.459,7.351 7.459,1.718 1.524,1.718 1.524,10.86
NetD316_1 on Top Layer "TOP_LAYER_NETD316_1_P050" (solid, remove dead copper, pour order 50): 18.459,10.86 18.459,8.066 20.338,8.066 20.338,7.351 18.459,7.351 18.459,1.718 12.7,1.718 12.7,10.86
NetD312_1 on Top Layer "TOP_LAYER_NETD312_1_P048" (solid, remove dead copper, pour order 48): 29.459,10.86 29.459,8.066 31.338,8.066 31.338,7.351 29.459,7.351 29.459,1.718 23.876,1.718 23.876,10.86
NetD308_1 on Top Layer "TOP_LAYER_NETD308_1_P046" (solid, remove dead copper, pour order 46): 40.459,10.86 40.459,8.066 42.338,8.066 42.338,7.351 40.459,7.351 40.459,1.718 34.798,1.718 34.798,10.86
NetD304_1 on Top Layer "TOP_LAYER_NETD304_1_P044" (solid, remove dead copper, pour order 44): 51.459,10.86 51.459,8.066 53.338,8.066 53.338,7.351 51.459,7.351 51.459,1.718 45.72,1.718 45.72,10.86
1OUT11 on Top Layer "TOP_LAYER_1OUT11_P042" (solid, remove dead copper, pour order 42): 7.636,10.86 7.636,8.32 9.541,8.32 9.541,7.05 7.636,7.05 7.636,1.716 12.564,1.716 12.564,10.86
1OUT10 on Top Layer "TOP_LAYER_1OUT10_P040" (solid, remove dead copper, pour order 40): 18.636,10.86 18.636,8.32 20.541,8.32 20.541,7.05 18.636,7.05 18.636,1.716 23.564,1.716 23.564,10.86
1OUT9 on Top Layer "TOP_LAYER_1OUT9_P038" (solid, remove dead copper, pour order 38): 29.636,10.86 29.636,8.32 31.541,8.32 31.541,7.05 29.636,7.05 29.636,1.716 34.564,1.716 34.564,10.86
1OUT8 on Top Layer "TOP_LAYER_1OUT8_P036" (solid, remove dead copper, pour order 36): 40.636,10.86 40.636,8.32 42.541,8.32 42.541,7.05 40.636,7.05 40.636,1.716 45.564,1.716 45.564,10.86
1OUT7 on Top Layer "TOP_LAYER_1OUT7_P034" (solid, remove dead copper, pour order 34): 51.636,10.86 51.636,8.32 53.541,8.32 53.541,7.05 51.636,7.05 51.636,1.716 56.564,1.716 56.564,10.86
NetD300_1 on Top Layer "TOP_LAYER_NETD300_1_P032" (solid, remove dead copper, pour order 32): 62.459,10.86 62.459,8.066 64.338,8.066 64.338,7.351 62.459,7.351 62.459,1.718 56.642,1.718 56.642,10.86
1OUT6 on Top Layer "TOP_LAYER_1OUT6_P030" (solid, remove dead copper, pour order 30): 62.636,10.86 62.636,8.32 64.541,8.32 64.541,7.05 62.636,7.05 62.636,1.716 67.564,1.716 67.564,10.86
NetD302_2 on Top Layer "TOP_LAYER_NETD302_2_P028" (solid, remove dead copper, pour order 28): 133.486,10.86 133.486,1.718 127.847,1.718 127.847,7.052 126.001,7.052 126.001,8.322 127.923,8.322 127.923,10.86
NetD306_2 on Top Layer "TOP_LAYER_NETD306_2_P026" (solid, remove dead copper, pour order 26): 122.486,10.86 122.486,1.718 116.847,1.718 116.847,7.052 115.037,7.052 115.037,8.322 116.923,8.322 116.923,10.86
